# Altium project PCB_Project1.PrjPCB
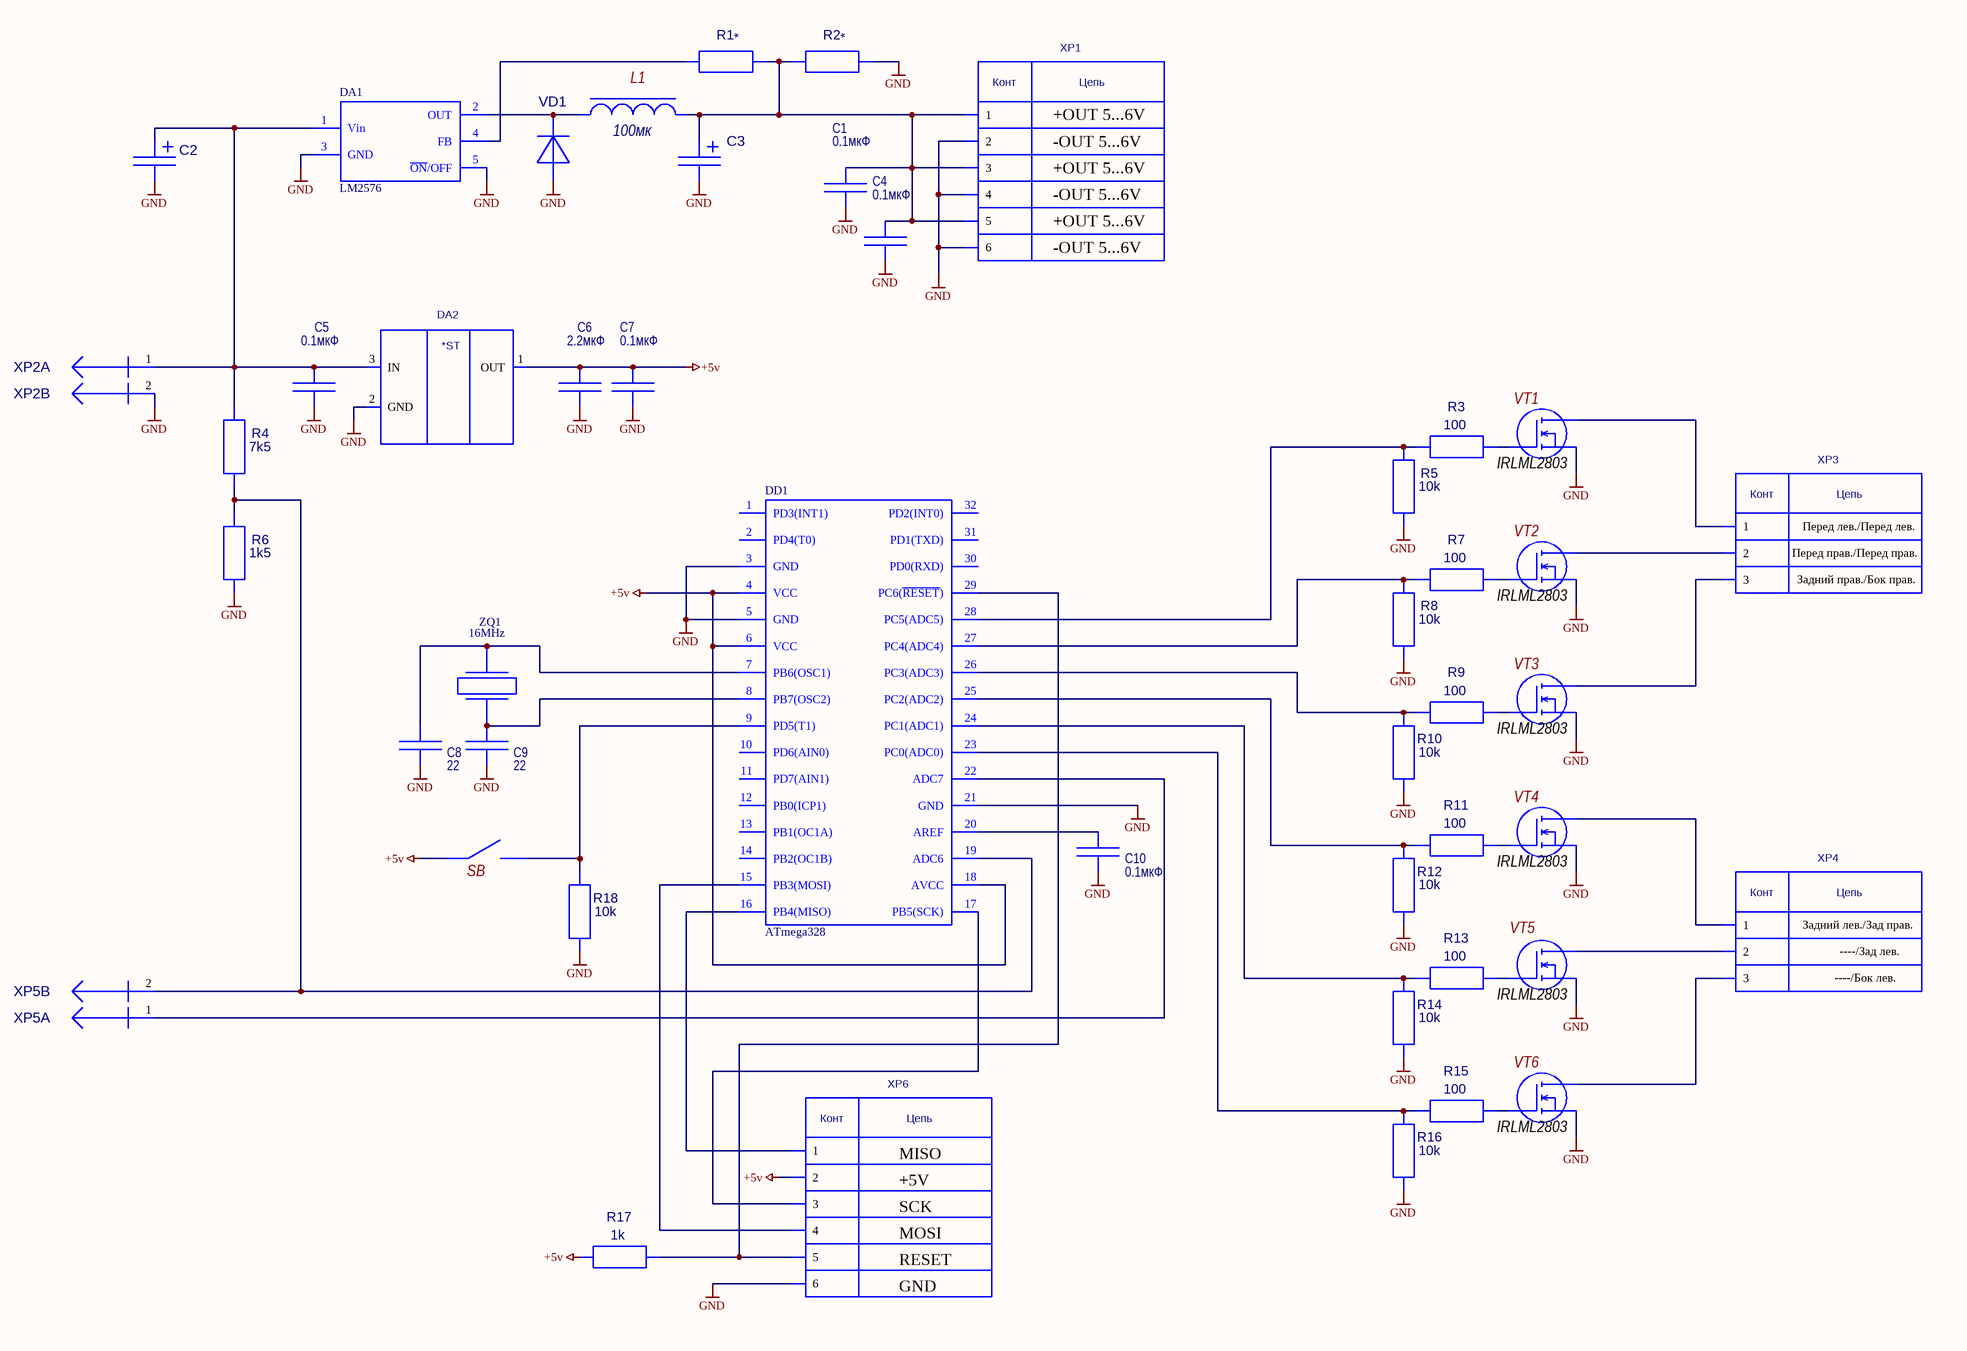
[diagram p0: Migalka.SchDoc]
1 sheet, 47 parts. Net scope: global (net labels, ports and power ports of the same name join across sheets).
Board file: PCB1.PcbDoc

## Sheet Migalka.SchDoc
size A2; Organization: Altium Limited; Address1: L3, 12a Rodborough Rd; Address2: Frenchs Forest; Address3: NSW; Address4: Australia 2086

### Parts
C1  value 0.1мкФ  [SMD0805]  (hidden comment: C0805)
C2  TAJ_SMD_E  [FT-SMD-E]  (value not drawn)
C3  TAJ_SMD_E  [FT-SMD-E]  (value not drawn)
C4  value 0.1мкФ  [SMD0805]  (hidden comment: C0805)
C5  value 0.1мкФ  [SMD0805]  (hidden comment: C0805)
C6  value 2.2мкФ  [SMD0805]  (hidden comment: C0805)
C7  value 0.1мкФ  [SMD0805]  (hidden comment: C0805)
C8  value 22  [SMD0805]  (hidden comment: C0805)
C9  value 22  [SMD0805]  (hidden comment: C0805)
C10  value 0.1мкФ  [SMD0805]  (hidden comment: C0805)
DA1  LM2576  [TO_220-5 smd]
DA2  TA78L05_F  [SOT-89]  (value not drawn)
DD1  ATmega328  [Quad32]
L1  100мк  [B82462]
R1  R0603  [SMD0603]  (value not drawn)
R2  R0603  [SMD0603]  (value not drawn)
R3  value 100  [SMD0603]  (hidden comment: R0603)
R4  value 7k5  [SMD0603]  (hidden comment: R0603)
R5  value 10k  [SMD0603]  (hidden comment: R0603)
R6  value 1k5  [SMD0603]  (hidden comment: R0603)
R7  value 100  [SMD0603]  (hidden comment: R0603)
R8  value 10k  [SMD0603]  (hidden comment: R0603)
R9  value 100  [SMD0603]  (hidden comment: R0603)
R10  value 10k  [SMD0603]  (hidden comment: R0603)
R11  value 100  [SMD0603]  (hidden comment: R0603)
R12  value 10k  [SMD0603]  (hidden comment: R0603)
R13  value 100  [SMD0603]  (hidden comment: R0603)
R14  value 10k  [SMD0603]  (hidden comment: R0603)
R15  value 100  [SMD0603]  (hidden comment: R0603)
R16  value 10k  [SMD0603]  (hidden comment: R0603)
R17  value 1k  [SMD0603]  (hidden comment: R0603)
R18  value 10k  [SMD0603]  (hidden comment: R0603)
SB  SB  (value not drawn)
VD1  10MQ040N  [SMA]  (value not drawn)
VT1  IRLML2803  [SOT23_FDV303N]
VT2  IRLML2803  [SOT23_FDV303N]
VT3  IRLML2803  [SOT23_FDV303N]
VT4  IRLML2803  [SOT23_FDV303N]
VT5  IRLML2803  [SOT23_FDV303N]
VT6  IRLML2803  [SOT23_FDV303N]
XP1  PLD_6R  [PLD_6R]  (value not drawn)
XP2  PLS_2R  [PLS_2R]  (value not drawn)  (parts A,B of 2)
XP3  PLS_3R  [PLS_3R]  (value not drawn)
XP4  PLS_3R  [PLS_3R]  (value not drawn)
XP5  PLS_2R  [PLS_2R]  (value not drawn)  (parts A,B of 2)
XP6  PLD_6R  [PLD_6R]  (value not drawn)
ZQ1  16MHz  [HC49SM]

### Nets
+5v: C6.1(i/o) C7.1(i/o) DA2.1(OUT) DD1.4(VCC) DD1.6(VCC) DD1.18(AVCC) R17.1(I/O0) SB.2 XP6.2
GND: C1.2(i/o1) C2.2(i/o1) C3.2(i/o1) C4.2(i/o1) C5.2(i/o1) C6.2(i/o1) C7.2(i/o1) C8.2(i/o1) C9.2(i/o1) C10.2(i/o1) DA1.3(GND) DA1.5(~{ON}/OFF) DA2.2(GND) DD1.3(GND) DD1.5(GND) DD1.21(GND) R2.1(I/O0) R5.1(I/O0) R6.1(I/O0) R8.1(I/O0) R10.1(I/O0) R12.1(I/O0) R14.1(I/O0) R16.1(I/O0) R18.1(I/O0) VD1.1 VT1.s VT2.s VT3.s VT4.s VT5.s VT6.s XP1.2 XP1.4 XP1.6 XP2.2(i/o) XP6.6
NetC1_1: C1.1(i/o) C3.1(i/o) C4.1(i/o) L1.2 R1.1(I/O0) R2.2(I/O1) XP1.1 XP1.3 XP1.5
NetC2_1: C2.1(i/o) C5.1(i/o) DA1.1(Vin) DA2.3(IN) R4.2(I/O1) XP2.1(i/o)
NetC8_1: C8.1(i/o) DD1.7(PB6(OSC1)) ZQ1.2
NetC9_1: C9.1(i/o) DD1.8(PB7(OSC2)) ZQ1.1
NetC10_1: C10.1(i/o) DD1.20(AREF)
NetDA1_2: DA1.2(OUT) L1.1 VD1.2
NetDA1_4: DA1.4(FB) R1.2(I/O1)
NetDD1_9: DD1.9(PD5(T1)) R18.2(I/O1) SB.1
NetDD1_15: DD1.15(PB3(MOSI)) XP6.4
NetDD1_16: DD1.16(PB4(MISO)) XP6.1
NetDD1_17: DD1.17(PB5(SCK)) XP6.3
NetDD1_19: DD1.19(ADC6) R4.1(I/O0) R6.2(I/O1) XP5.2(i/o)
NetDD1_22: DD1.22(ADC7) XP5.1(i/o)
NetDD1_23: DD1.23(PC0(ADC0)) R15.1(I/O0) R16.2(I/O1)
NetDD1_24: DD1.24(PC1(ADC1)) R13.1(I/O0) R14.2(I/O1)
NetDD1_25: DD1.25(PC2(ADC2)) R11.1(I/O0) R12.2(I/O1)
NetDD1_26: DD1.26(PC3(ADC3)) R9.1(I/O0) R10.2(I/O1)
NetDD1_27: DD1.27(PC4(ADC4)) R7.1(I/O0) R8.2(I/O1)
NetDD1_28: DD1.28(PC5(ADC5)) R3.1(I/O0) R5.2(I/O1)
NetDD1_29: DD1.29(PC6(~{RESET})) R17.2(I/O1) XP6.5
NetR3_2: R3.2(I/O1) VT1.g
NetR7_2: R7.2(I/O1) VT2.g
NetR9_2: R9.2(I/O1) VT3.g
NetR11_2: R11.2(I/O1) VT4.g
NetR13_2: R13.2(I/O1) VT5.g
NetR15_2: R15.2(I/O1) VT6.g
NetVT1_d: VT1.d XP3.1
NetVT2_d: VT2.d XP3.2
NetVT3_d: VT3.d XP3.3
NetVT4_d: VT4.d XP4.1
NetVT5_d: VT5.d XP4.2
NetVT6_d: VT6.d XP4.3

Not connected (* = marked no-connect by the designer): DD1 1(PD3(INT1)) 2(PD4(T0)) 10(PD6(AIN0)) 11(PD7(AIN1)) 12(PB0(ICP1)) 13(PB1(OC1A)) 14(PB2(OC1B)) 30(PD0(RXD)) 31(PD1(TXD)) 32(PD2(INT0))

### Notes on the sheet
- +OUT 5...6V
- -OUT 5...6V
- Перед лев./Перед лев.
- Перед прав./Перед прав.
- Задний прав./Бок прав.
- Задний лев./Зад прав.
- ----/Бок лев.
- ----/Зад лев.
- MISO
- +5V
- SCK
- MOSI
- RESET
- GND

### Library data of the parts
C2 C3 = TAJ_SMD_E: Value: {Value}
DA2 = TA78L05_F: Value: {Value}
L1 = L_1: Inductor with ferromag. core
SB = SB: Button
VD1 = 10MQ040N: Value: {Value}
VT1-VT6 = FDV303N: IGFET(P)
XP1 XP6 = PLD_6R: Value: {Value}
XP3 XP4 = PLS_3R: Value: {Value}
ZQ1 = ZQ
